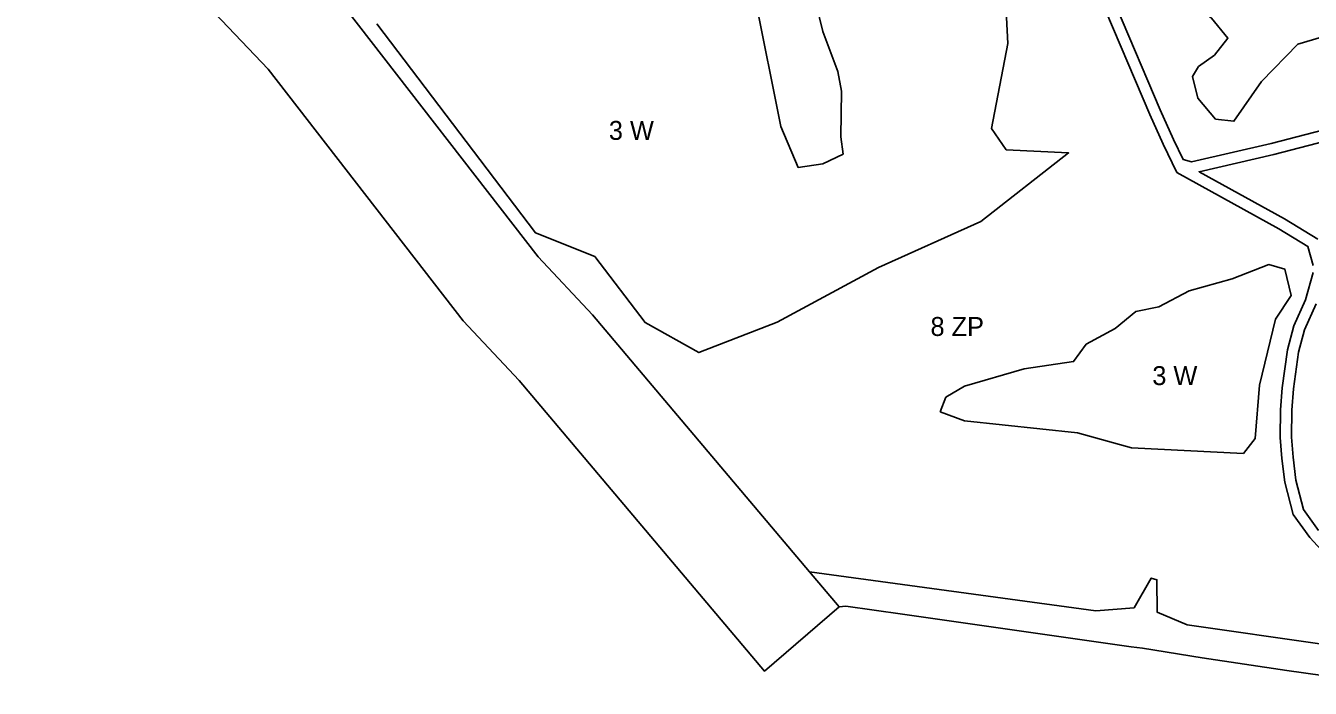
# Model space of a CAD drawing. Extents: x 7437831 to 7440315, y 5545798 to 5547888.
# Drawn here: x 7438028 to 7438706, y 5546102 to 5546452 of the extents above; entities that cross this region are included whole.
import ezdxf

# ---------------------------------------------------------------- set-up
doc = ezdxf.new("R2010")
doc.units = 0
doc.layers.add('linie_rozgraniczajace', color=7, linetype='Continuous')
doc.layers.add('oznaczenia_przeznaczen', color=7, linetype='Continuous')

msp = doc.modelspace()

# ---------------------------------------------------------------- linework, layer by layer
at = {"layer": 'linie_rozgraniczajace'}
for points in [[(7438795.44, 5546418.73), (7438685.57, 5546390.27), (7438643.52, 5546380.52), (7438639.21, 5546381.67), (7438634.01, 5546392.39), (7438626.97, 5546407.98), (7438603.87, 5546462.25), (7438595.94, 5546482.98), (7438585.8, 5546504.48), (7438579.13, 5546521.56), (7438575.01, 5546530.35), (7438532.66, 5546578.21), (7438521, 5546592.78), (7438500.73, 5546617.61), (7438487.78, 5546634.71), (7438490.58, 5546638.54), (7438510.63, 5546640.5), (7438562.77, 5546645.99), (7438656.58, 5546659.83), (7438680.41, 5546662.55), (7438691.52, 5546667.32), (7438699.06, 5546673.83), (7438708.8, 5546695.84)], [(7438708.8, 5546695.84), (7438699.06, 5546673.83), (7438691.52, 5546667.32), (7438680.41, 5546662.55), (7438656.58, 5546659.83), (7438562.77, 5546645.99), (7438510.63, 5546640.5), (7438490.58, 5546638.54), (7438487.78, 5546634.71), (7438500.73, 5546617.61), (7438521, 5546592.78), (7438532.66, 5546578.21), (7438575.01, 5546530.35), (7438579.13, 5546521.56), (7438585.8, 5546504.48), (7438595.94, 5546482.98), (7438603.87, 5546462.25), (7438626.97, 5546407.98), (7438634.01, 5546392.39), (7438639.21, 5546381.67), (7438643.52, 5546380.52), (7438685.57, 5546390.27), (7438795.44, 5546418.73)], [(7438707.78, 5546325.74), (7438705.04, 5546335.85), (7438689.64, 5546345.13), (7438659.33, 5546361.84), (7438635.81, 5546374.92), (7438628.58, 5546389.85), (7438621.47, 5546405.58), (7438598.3, 5546460), (7438590.41, 5546480.63), (7438580.28, 5546502.11), (7438573.27, 5546520.07), (7438528.01, 5546574.42), (7438516.33, 5546589.01), (7438496.01, 5546613.9), (7438482.25, 5546632.08)], [(7438196.67, 5546461.27), (7438298.35, 5546330.31), (7438327.02, 5546299.69), (7438441.63, 5546163.98), (7438457.31, 5546145.41), (7438417.85, 5546111.55), (7438288.22, 5546265.05), (7438258.75, 5546296.53), (7438155.6, 5546429.38), (7438109.87, 5546477.65), (7438028.21, 5546571.79), (7438027.55, 5546572.58)], [(7438735.57, 5546569.53), (7438699.95, 5546549.81), (7438634.72, 5546543.09), (7438625.39, 5546547.96), (7438608.24, 5546551.18), (7438598.55, 5546545.46), (7438586.82, 5546525.85), (7438597.33, 5546504.17), (7438611.07, 5546480.91), (7438636.69, 5546470.6), (7438654.01, 5546456.4), (7438662.73, 5546445.9), (7438655.6, 5546436.86), (7438647.14, 5546430.84), (7438644.08, 5546425.54), (7438646.83, 5546414.2), (7438656.25, 5546403.03), (7438665.92, 5546401.94), (7438680.49, 5546422.88), (7438699.67, 5546442.72), (7438716.97, 5546447.82)], [(7438716.97, 5546447.82), (7438699.67, 5546442.72), (7438680.49, 5546422.88), (7438665.92, 5546401.94), (7438656.25, 5546403.03), (7438646.83, 5546414.2), (7438644.08, 5546425.54), (7438647.14, 5546430.84), (7438655.6, 5546436.86), (7438662.73, 5546445.9), (7438654.01, 5546456.4), (7438636.69, 5546470.6), (7438611.07, 5546480.91), (7438597.33, 5546504.17), (7438586.82, 5546525.85), (7438598.55, 5546545.46), (7438608.24, 5546551.18), (7438625.39, 5546547.96), (7438634.72, 5546543.09), (7438699.95, 5546549.81), (7438735.57, 5546569.53)], [(7438213.04, 5546453.35), (7438296.89, 5546343), (7438328.2, 5546330.55), (7438354.83, 5546295.64), (7438383.24, 5546279.73), (7438424.58, 5546295.87), (7438478.2, 5546324.66), (7438532.3, 5546349.06), (7438578.56, 5546385.23), (7438545.65, 5546386.87), (7438537.89, 5546398.07), (7438546.51, 5546443.09), (7438543.27, 5546504.72)], [(7438543.27, 5546504.72), (7438546.51, 5546443.09), (7438537.89, 5546398.07), (7438545.65, 5546386.87), (7438578.56, 5546385.23), (7438532.3, 5546349.06), (7438478.2, 5546324.66), (7438424.58, 5546295.87), (7438383.24, 5546279.73), (7438354.83, 5546295.64), (7438328.2, 5546330.55), (7438296.89, 5546343), (7438213.04, 5546453.35)], [(7438441.42, 5546479.8), (7438448.79, 5546449.27), (7438456.71, 5546428.19), (7438458.67, 5546417.77), (7438458.21, 5546393.64), (7438459.42, 5546384.56), (7438448.67, 5546379.45), (7438435.77, 5546377.48), (7438426.51, 5546399.09), (7438413.02, 5546467.01)], [(7438413.02, 5546467.01), (7438426.51, 5546399.09), (7438435.77, 5546377.48), (7438448.67, 5546379.45), (7438459.42, 5546384.56), (7438458.21, 5546393.64), (7438458.67, 5546417.77), (7438456.71, 5546428.19), (7438448.79, 5546449.27), (7438441.42, 5546479.8)], [(7438855.21, 5546105.38), (7438641.23, 5546135.98), (7438625.4, 5546142.59), (7438625.24, 5546159.75), (7438622.25, 5546160.7), (7438613.23, 5546145.04), (7438592.9, 5546143.41), (7438441.63, 5546163.98), (7438327.02, 5546299.69), (7438298.35, 5546330.31), (7438196.67, 5546461.27)], [(7438598.3, 5546460), (7438621.47, 5546405.58), (7438628.58, 5546389.85), (7438635.81, 5546374.92), (7438659.33, 5546361.84), (7438689.64, 5546345.13), (7438705.04, 5546335.85), (7438707.78, 5546325.74)], [(7438710.19, 5546339.75), (7438692.64, 5546350.33), (7438647.5, 5546375.29), (7438687, 5546384.45), (7438796.92, 5546412.91)], [(7438796.92, 5546412.91), (7438687, 5546384.45), (7438647.5, 5546375.29), (7438692.64, 5546350.33), (7438710.19, 5546339.75)], [(7438707.86, 5546322.08), (7438703.79, 5546307.58), (7438697.52, 5546293.88), (7438694.22, 5546281.2), (7438691.38, 5546261.17), (7438690.57, 5546249.61), (7438690.35, 5546234.94), (7438691.3, 5546223.88), (7438692.79, 5546211.27), (7438697.21, 5546194.29), (7438706.01, 5546182.06), (7438714.2, 5546173.33)], [(7438714.2, 5546173.33), (7438706.01, 5546182.06), (7438697.21, 5546194.29), (7438692.79, 5546211.27), (7438691.3, 5546223.88), (7438690.35, 5546234.94), (7438690.57, 5546249.61), (7438691.38, 5546261.17), (7438694.22, 5546281.2), (7438697.52, 5546293.88), (7438703.79, 5546307.58), (7438707.86, 5546322.08)], [(7438710.65, 5546185.88), (7438702.73, 5546196.88), (7438698.7, 5546212.38), (7438697.27, 5546224.49), (7438696.35, 5546235.16), (7438696.56, 5546249.35), (7438697.35, 5546260.54), (7438700.11, 5546280.02), (7438703.19, 5546291.86), (7438709.44, 5546305.5)], [(7438709.44, 5546305.5), (7438703.19, 5546291.86), (7438700.11, 5546280.02), (7438697.35, 5546260.54), (7438696.56, 5546249.35), (7438696.35, 5546235.16), (7438697.27, 5546224.49), (7438698.7, 5546212.38), (7438702.73, 5546196.88), (7438710.65, 5546185.88)], [(7438760.54, 5546102.46), (7438693.97, 5546111.88), (7438649.22, 5546118.54), (7438617.68, 5546123.63), (7438611.72, 5546124.34), (7438557.39, 5546132.05), (7438490.76, 5546141.69), (7438460.97, 5546145.85), (7438457.31, 5546145.41), (7438441.63, 5546163.98), (7438592.9, 5546143.41), (7438613.23, 5546145.04), (7438622.25, 5546160.7), (7438625.24, 5546159.75), (7438625.4, 5546142.59), (7438641.23, 5546135.98), (7438855.21, 5546105.38)]]:
    msp.add_lwpolyline(points, dxfattribs=at)
for points in [[(7438510.67, 5546248.5), (7438523.5, 5546243.78), (7438583.37, 5546237.35), (7438611.82, 5546229.49), (7438670.92, 5546226.46), (7438677.15, 5546234.37), (7438679.37, 5546262.5), (7438687.87, 5546297.39), (7438696.14, 5546309.94), (7438692.91, 5546323.75), (7438684.41, 5546326.27), (7438665.06, 5546318.8), (7438642.23, 5546312.34), (7438626.35, 5546303.87), (7438614.05, 5546301.46), (7438603.16, 5546292.43), (7438587.84, 5546284.18), (7438581.18, 5546275.05), (7438555.04, 5546271.13), (7438523.66, 5546262.05), (7438513.74, 5546256.18)], [(7438510.67, 5546248.5), (7438513.74, 5546256.18), (7438523.66, 5546262.05), (7438555.04, 5546271.13), (7438581.18, 5546275.05), (7438587.84, 5546284.18), (7438603.16, 5546292.43), (7438614.05, 5546301.46), (7438626.35, 5546303.87), (7438642.23, 5546312.34), (7438665.06, 5546318.8), (7438684.41, 5546326.27), (7438692.91, 5546323.75), (7438696.14, 5546309.94), (7438687.87, 5546297.39), (7438679.37, 5546262.5), (7438677.15, 5546234.37), (7438670.92, 5546226.46), (7438611.82, 5546229.49), (7438583.37, 5546237.35), (7438523.5, 5546243.78)]]:
    msp.add_lwpolyline(points, close=True, dxfattribs=at)

# ---------------------------------------------------------------- texts
at = {"layer": 'oznaczenia_przeznaczen'}
for s, p in [('3 W', (7438335.6843, 5546392.11)), ('8 ZP', (7438505.6229, 5546288.55)), ('3 W', (7438622.8243, 5546262.6))]:
    msp.add_text(s, height=10, dxfattribs=at).set_placement(p)

doc.saveas('drawing.dxf')
